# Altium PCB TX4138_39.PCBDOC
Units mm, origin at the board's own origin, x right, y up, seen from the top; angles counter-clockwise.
Board outline 46.99 x 45.72 mm, 2 copper layers (TopLayer, BottomLayer); 17 components, 15 nets, 50 pads, 35 vias.
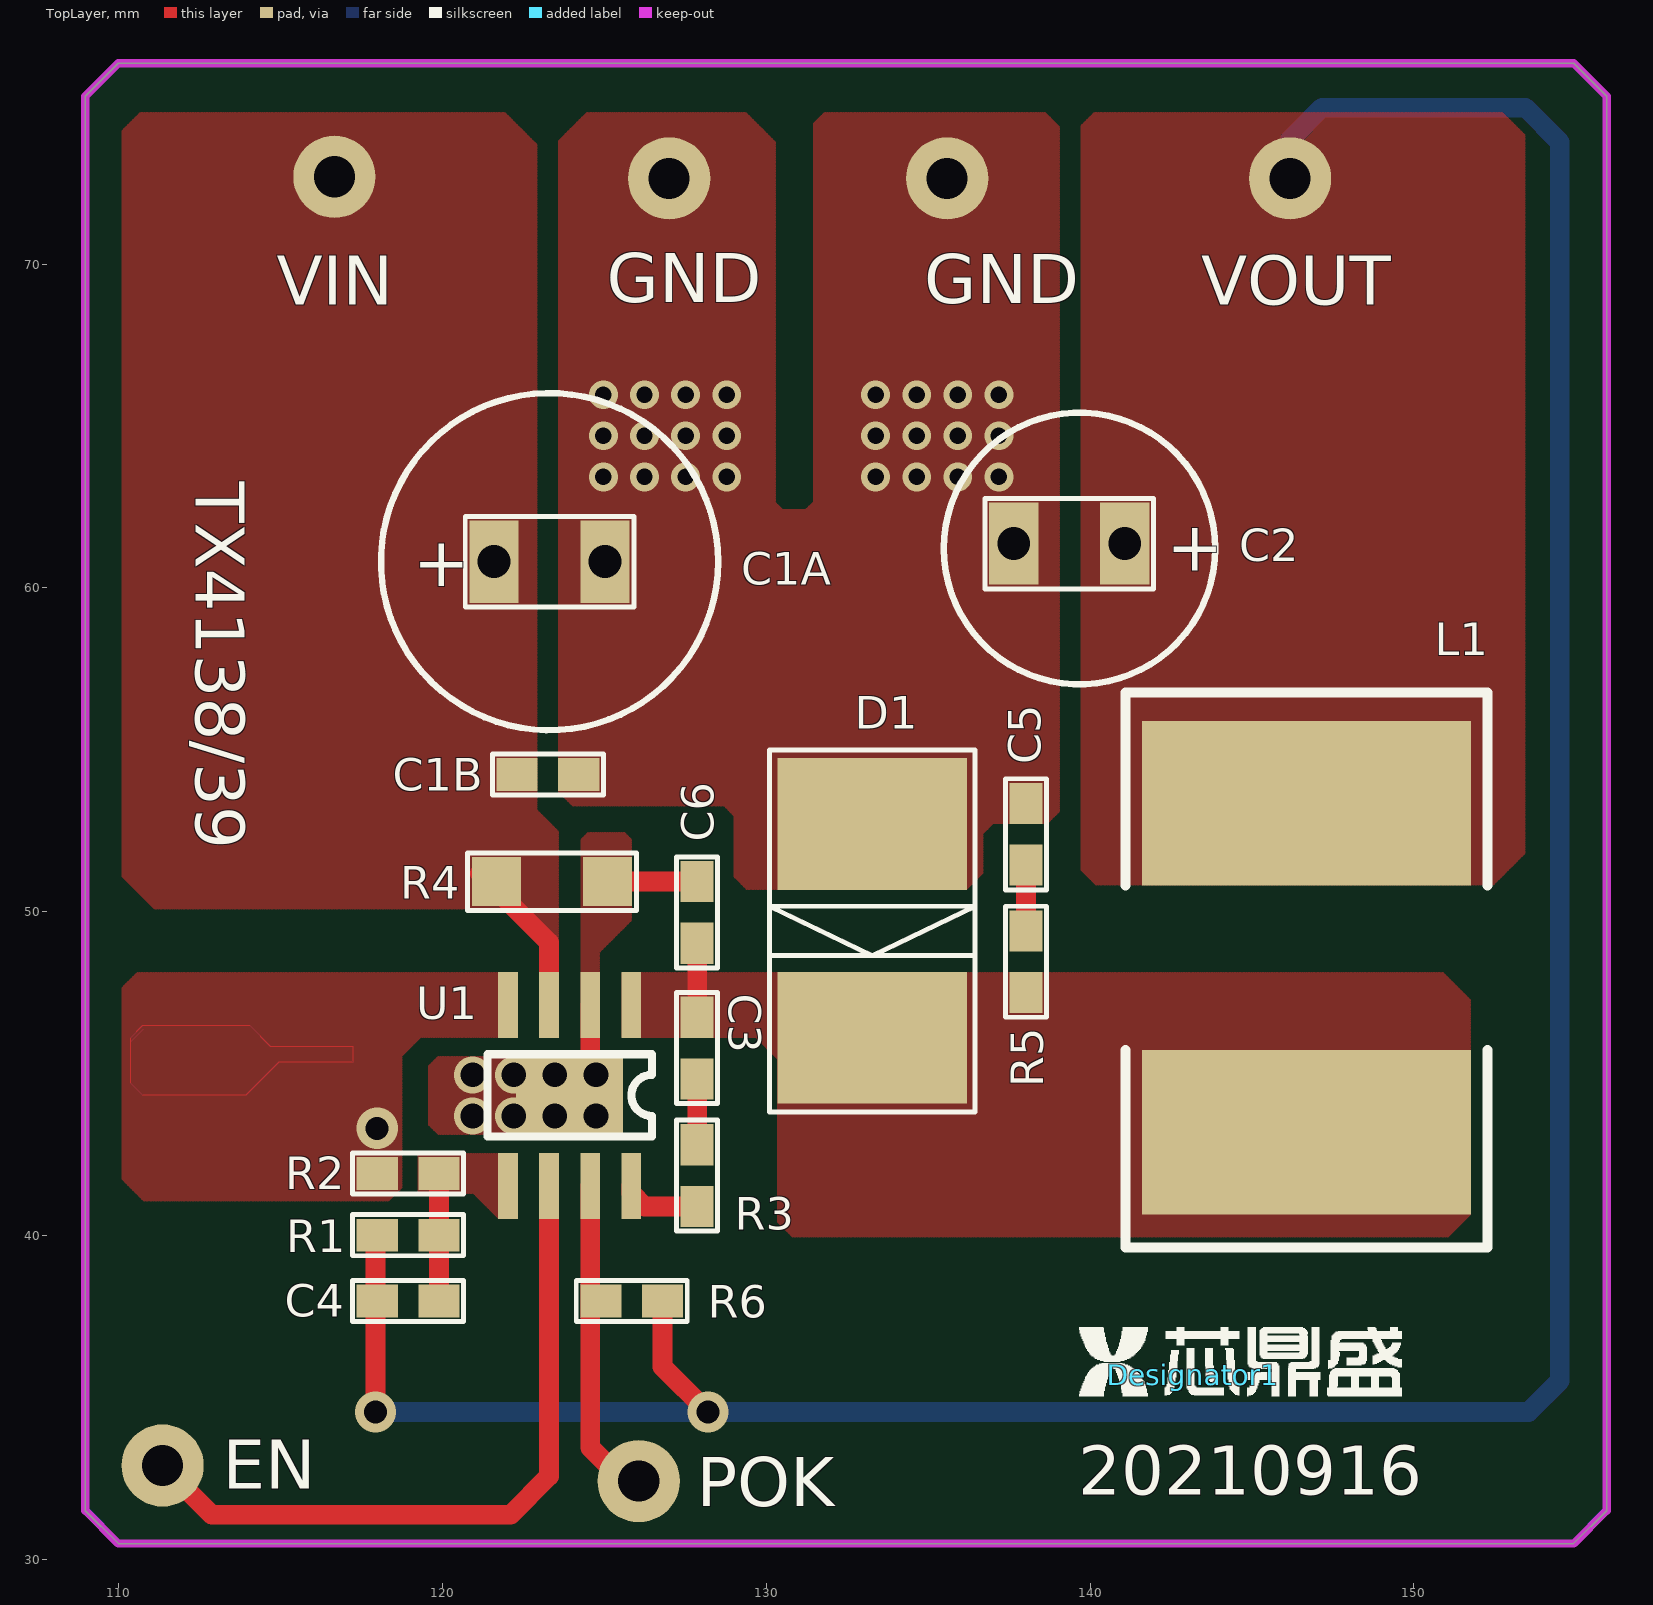
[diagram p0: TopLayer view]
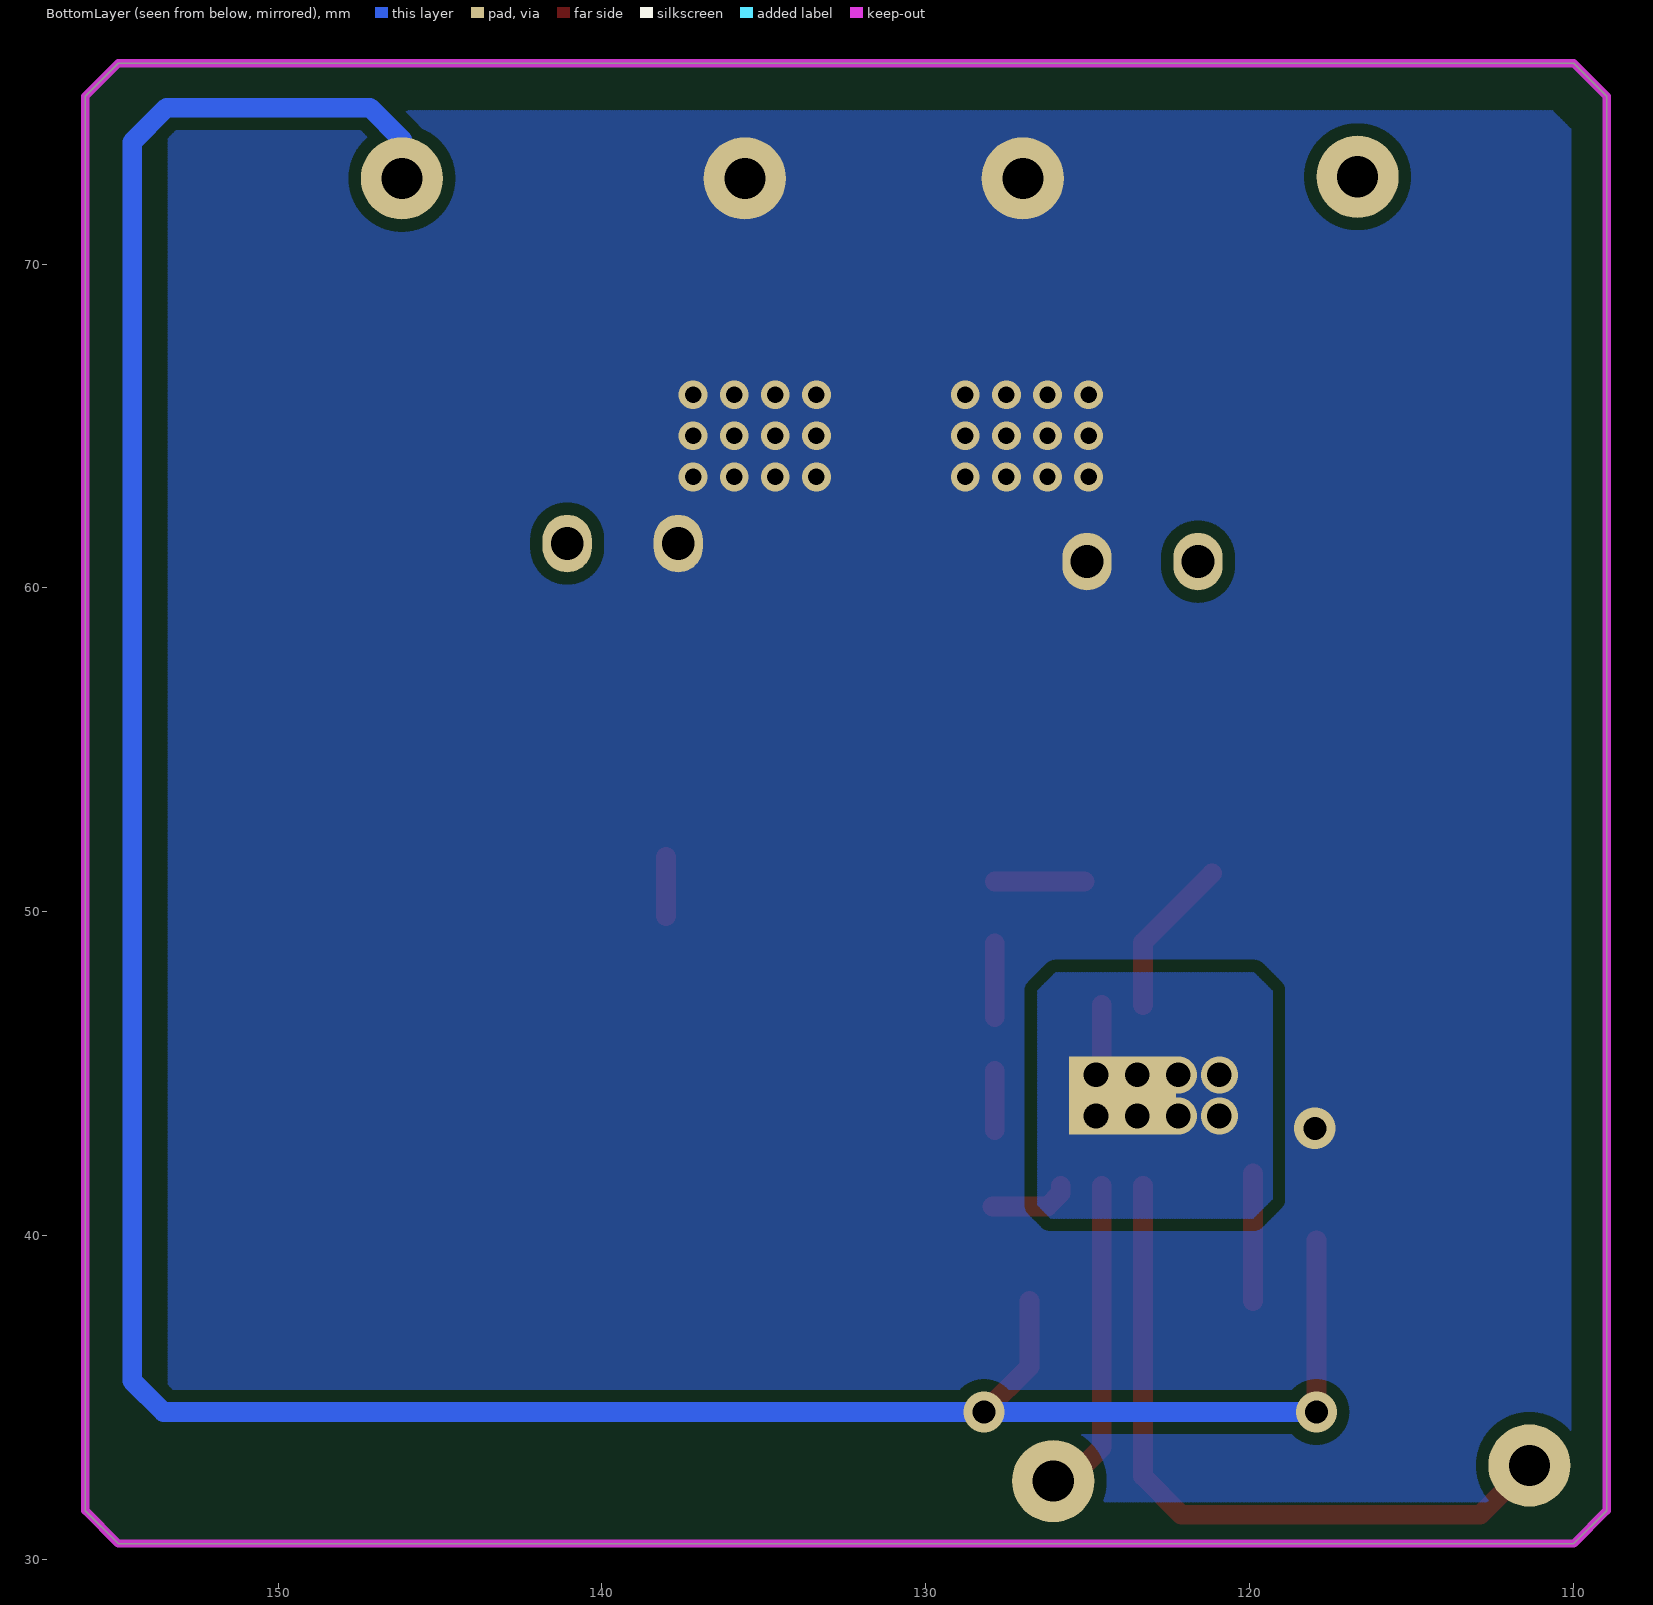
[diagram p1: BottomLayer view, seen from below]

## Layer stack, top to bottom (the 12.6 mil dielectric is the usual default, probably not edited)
TopSolder: solder mask 0.0102, Solder Resist, Dk 3.5
TopLayer: signal copper 0.0356
Dielectric1: dielectric 0.32, FR-4, Dk 4.8
BottomLayer: signal copper 0.0356
BottomSolder: solder mask 0.0102, Solder Resist, Dk 3.5

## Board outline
108.966,31.496 108.966,75.184 109.982,76.2 154.94,76.2 155.956,75.184 155.956,31.496 154.94,30.48 109.982,30.48

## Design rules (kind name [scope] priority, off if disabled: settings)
Clearance Clearance_1 [OnLayer('BottomLayer')] p1: gap=0.381 ignorepadtopadclearanceinfootprint=FALSE
Clearance [All] p2: gap=0.254 ignorepadtopadclearanceinfootprint=FALSE
FabricationTestPointUsage TestPointUsage [All] p1: valid=0 allowmultiple=FALSE
FabricationTestpoint Testpoint [All] p1: side=3 testpointundercomponent=TRUE minsize=1.016 maxsize=2.54 preferedsize=1.524 minholesize=0.508 maxholesize=1.016 preferedholesize=0.813 testpointgrid=0.025 allowsidetop=TRUE allowsidebottom=TRUE usegrid=TRUE gridtolerance=0
PolygonConnect [All] p1: connectstyle=Direct reliefconductorwidth=0.254 reliefentries=4 polygonreliefangle="90 Angle" airgapwidth=0.254
RoutingVias [All] p1: holewidth=0.508 width=0.889 viastyle="Through Hole" minholewidth=0.711 minwidth=1.27 maxholewidth=0.711 maxwidth=1.27
SolderMaskExpansion [All] p1: expansion=0.102 istentingtop=FALSE
Width [All] p1: maxlimit=1.27 minlimit=0.254 preferedwidth=0.61
28 further rules are at their usual default settings.

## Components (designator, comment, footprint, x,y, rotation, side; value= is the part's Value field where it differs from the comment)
C1A "10uF/50V" 1210 121.59,60.808 r0 top
C1B "100nF" 0603 122.301,54.229 r0 top
C2 "22uF/25V" 1210 141.072,61.366 r180 top
C3 "30R" 0603 127.864,44.831 r90 top
C4 "300K" 0603 117.983,37.973 r0 top
C5 "30R" 0603 138.024,51.435 r90 top
C6 "100nF" 0603 127.864,49.022 r90 top
D1 "SK34B" SMC 133.274,52.705 r270 top
Designator1 "Comment" LOGO(10x2)mm 143.18,35.69 r0 top
L1 "" CD125 146.685,43.18 r90 top
R1 "22pF" 0603 117.983,40.005 r0 top
R2 "57.1K" 0603 119.888,41.91 r180 top
R3 "10nF" 0603 127.864,42.799 r270 top
R4 "R040" 1206 125.095,50.927 r180 top
R5 "10nF" 0603 138.024,49.403 r270 top
R6 "22pF" 0603 126.797,37.973 r180 top
U1 "" ESOP-8 125.832,47.117 r270 top

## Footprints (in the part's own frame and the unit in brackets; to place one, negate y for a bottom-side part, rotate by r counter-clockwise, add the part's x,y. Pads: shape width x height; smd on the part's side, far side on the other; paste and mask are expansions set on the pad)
0603 [mil]
  rect 50x40 smd: 1(0,0) 2(75,0)
  silkscreen extent -30,-25 105,25
1206 [mil]
  rect 60x60 smd: 1(0,0) 2(135,0)
  silkscreen extent -35,-35 170,35
1210 [mil]
  rect 60x100 smd: 1(0,0) 2(135,0)
  silkscreen extent -35,-55 170,55
CD125 [mm]
  rect 5.08x10.16 smd: 1(0,0) 2(10.16,0)
  silkscreen extent -3.56,-5.59 13.59,5.59
ESOP-8 [mil]
  rect 80x24 smd: 1(0,0) 2(0,-50) 3(0,-100) 4(0,-150) 5(220,-150) 6(220,-100) 7(220,-50) 8(220,0)
  rect 95x130 smd: 9(110,-75)
  rect 95x130 smd far side: 9(110,-75)
  silkscreen extent 60,-175 160,25
LOGO(10x2)mm [mm]
  silkscreen extent -3.52,-0.65 6.44,1.47
SMC [mil]
  rect 160x230 smd: 1(0,0) 2(260,0)
  silkscreen extent -90,-125 350,125

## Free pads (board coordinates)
  round 2.54 hole 1.27: 1(111.354,32.893) 1(116.662,72.695) 1(126.06,32.41) 1(127,72.644) 1(135.585,72.644) 1(146.177,72.644)
  oval 1.524x1.778 hole 1.016: 1(121.59,60.808) 1(137.643,61.366) ""(125.019,60.808) ""(141.072,61.366)

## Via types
v1: diameter 0.889, hole 0.508, TopLayer to BottomLayer, 24 vias
v2: diameter 1.143, hole 0.762, TopLayer to BottomLayer, 8 vias
v3: diameter 1.27, hole 0.711, TopLayer to BottomLayer, 3 vias

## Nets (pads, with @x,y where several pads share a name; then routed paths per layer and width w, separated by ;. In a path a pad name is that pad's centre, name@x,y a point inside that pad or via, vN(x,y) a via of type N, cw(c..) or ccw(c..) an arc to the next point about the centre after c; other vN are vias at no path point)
BST: R3.2 U1.8 | length 2.5
  TopLayer w0.61: U1.8 125.832,41.3 126.238,40.894 R3.2@127.94,40.894
EN: pad.1@111.354,32.893 U1.6 | length 22
  TopLayer w0.61: pad.1@111.354,32.893 112.878,31.369 122.098,31.369 123.292,32.563 U1.6
EN1: 
FB: C4.2 R1.2 R2.1 U1.5 | length 3.9
  TopLayer w0.61: C4.2 R2.1
GATE: 
GND: C1A.2 C1B.2 C2.2 C5.2 D1.1 pad.1@127,72.644 pad.1@135.585,72.644 pad.1@137.643,61.366 pad.@125.019,60.808 R2.2 U1.4
  other v1: 124.968,63.424 126.238,63.424 127.508,63.424 128.778,63.424 133.375,63.424 134.645,63.424 135.915,63.424 137.185,63.424 124.968,64.694 126.238,64.694 127.508,64.694 128.778,64.694 133.375,64.694 134.645,64.694 135.915,64.694 137.185,64.694 124.968,65.964 126.238,65.964 127.508,65.964 128.778,65.964 133.375,65.964 134.645,65.964 135.915,65.964 137.185,65.964
  other v3: 117.983,43.307
ILIM: C6.2 R4.1 U1.2 U1.9 | length 5.8
  TopLayer w0.61: U1.9@123.927,44.323 124.562,44.958 U1.2 ; R4.1 C6.2
  other v2: 120.929,43.688 122.199,43.688 123.469,43.688 124.739,43.688 120.929,44.958 122.199,44.958 123.469,44.958 124.739,44.958
OUT: C2.1 C4.1 L1.2 pad.1@146.177,72.644 pad.@141.072,61.366 R1.1 R6.1 | length 95
  TopLayer w0.61: v3(117.932,34.544) R1.1@117.932,39.853 ; R6.1 126.797,35.941 v3(128.194,34.544)
  BottomLayer w0.61: v3@117.907,34.569 v3(117.932,34.544) 153.543,34.544 154.508,35.509 154.508,73.762 153.441,74.828 147.168,74.828 146.177,73.838 pad.1@146.177,72.644
POK: pad.1@126.06,32.41 R6.2 U1.7 | length 10
  TopLayer w0.61: U1.7 124.562,33.452 125.603,32.41 pad.1@126.06,32.41
RC1: 
SS: 
SW: C3.2 C6.1 D1.2 L1.1 R5.2 U1.1 | length 2.3
  TopLayer w0.61: C3.2 C6.1
sw-bst: C3.1 R3.1 | length 1.8
  TopLayer w0.61: R3.1@127.864,43.256 C3.1@127.864,45.085
VIN: C1A.1 C1B.1 pad.1@116.662,72.695 pad.1@121.59,60.808 R4.2 U1.3 | length 4.9
  TopLayer w0.61: R4.2@121.158,51.181 123.292,49.047 U1.3
VPOK: 
pads on no net: C5.1 R5.1
copper on no net: | length 1.8
  TopLayer w0.61: 138.024,49.86 138.024,51.689

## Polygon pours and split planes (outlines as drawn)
GND on TopLayer "TopLayer-GND" (hatched 90Degree grid 0.025 track 0.051, remove dead copper, pour order 0): 131.47,69.723 131.47,71.831 139.04,71.831 139.04,69.723
GND on TopLayer "TopLayer-GND 1" (hatched 90Degree grid 0.025 track 0.051, remove dead copper, pour order 1): 122.301,46.126 119.329,46.126 118.745,45.542 118.745,41.478 118.339,41.072 110.769,41.072 110.109,41.732 110.109,47.65 110.566,48.108 122.301,48.108
ILIM on TopLayer "TopLayer-ILIM" (hatched 90Degree grid 0.025 track 0.051, remove dead copper, pour order 2): 125.552,45.517 119.863,45.517 119.583,45.237 119.583,43.409 119.863,43.129 125.552,43.129
FB on TopLayer "TopLayer-FB" (hatched 90Degree grid 0.025 track 0.051, remove dead copper, pour order 3): 122.301,42.52 119.253,42.52 119.253,41.3 120.955,41.3 121.717,40.538 122.301,40.538
GND on TopLayer "TopLayer-GND 2" (hatched 90Degree grid 0.025 track 0.051, remove dead copper, pour order 4): 134.29,70.993 138.532,70.993 139.04,71.501 139.04,74.244 138.608,74.676 131.801,74.676 131.47,74.346 131.47,71.476 131.953,70.993
GND on TopLayer "TopLayer-GND 3" (hatched 90Degree grid 0.025 track 0.051, remove dead copper, pour order 5): 132.994,50.698 136.195,50.698 136.677,51.181 136.677,52.4 137.008,52.73 138.684,52.73 139.04,53.086 139.04,69.952 131.47,69.952 131.47,62.662 131.216,62.408 130.505,62.408 130.277,62.636 130.277,73.762 129.362,74.676 124.46,74.676 123.596,73.812 123.596,53.696 124.028,53.264 128.702,53.264 129.007,52.959 129.007,51.079 129.388,50.698
OUT on TopLayer "TopLayer-OUT" (hatched 90Degree grid 0.025 track 0.051, remove dead copper, pour order 6): 139.725,58.623 139.725,51.283 140.183,50.825 152.451,50.825 153.416,51.791 153.416,73.99 152.73,74.676 140.132,74.676 139.725,74.27 139.725,65.405 139.725,60.198
VIN on TopLayer "TopLayer-VIN" (hatched 90Degree grid 0.025 track 0.051, remove dead copper, pour order 7): 123.571,48.412 123.571,52.476 122.911,53.137 122.911,73.685 121.92,74.676 110.668,74.676 110.109,74.117 110.109,51.079 111.1,50.089 121.895,50.089
SW on TopLayer "TopLayer-SW" (hatched 90Degree grid 0.025 track 0.051, remove dead copper, pour order 8): 125.552,48.108 150.901,48.108 151.74,47.269 151.74,40.64 151.054,39.954 130.81,39.954 130.353,40.411 130.353,45.441 129.667,46.126 125.552,46.126
GND on TopLayer "TopLayer-GND 4" (hatched 90Degree grid 0.025 track 0.051, remove dead copper, pour order 9): 125.705,48.285
VIN on TopLayer "TopLayer-VIN 1" (hatched 90Degree grid 0.025 track 0.051, remove dead copper, pour order 10): 126.721,49.53
SW on TopLayer "TopLayer-SW 1" (hatched 90Degree grid 0.025 track 0.051, remove dead copper, pour order 11): 140.36,53.645
SW on TopLayer "TopLayer-SW 2" (hatched 90Degree grid 0.025 track 0.203, pour order 12): 47.117,38.862
SW on TopLayer "TopLayer-SW 3" (hatched 90Degree grid 0.102 track 0.025, remove dead copper, pour order 13): 47.117,41.783
VIN on TopLayer "TopLayer-VIN 2" (hatched 90Degree grid 0.025 track 0.102, remove dead copper, pour order 14): 41.656,41.021
VIN on TopLayer "TopLayer-VIN 3" (hatched 90Degree grid 0.025 track 0.102, remove dead copper, pour order 15): 28.067,45.212
VIN on TopLayer "TopLayer-VIN 4" (hatched 90Degree grid 0.025 track 0.102, remove dead copper, pour order 16): 73.66,41.783 72.136,41.783 71.374,41.021 71.374,39.878 70.231,38.735 56.515,38.735 55.372,37.592 52.578,37.592 51.816,36.83
VIN on TopLayer "TopLayer-VIN 5" (hatched 90Degree grid 0.025 track 0.102, remove dead copper, pour order 17): 116.967,45.339 114.935,45.339 113.919,44.323 110.744,44.323 110.363,44.704 110.363,45.974 110.744,46.355 110.363,45.974 110.363,46.101 110.744,46.482 114.046,46.482 114.681,45.847 117.221,45.847 117.221,45.339
ILIM on TopLayer "TopLayer-ILIM 1" (hatched 90Degree grid 0.025 track 0.051, remove dead copper, pour order 18): 124.282,46.126 124.841,46.126 124.841,48.743 125.832,49.733 125.832,52.222 125.628,52.426 124.485,52.426 124.282,52.222
ILIM on BottomLayer "BottomLayer-ILIM" (hatched 90Degree grid 0.025 track 0.051, remove dead copper, pour order 19): 119.304,47.346 119.304,41.123 119.888,40.538 126.136,40.538 126.543,40.945 126.543,47.549 125.984,48.108 119.863,48.108 119.304,47.549
VIN on BottomLayer "BottomLayer-VIN" (hatched 90Degree grid 0.025 track 0.102, remove dead copper, pour order 20): 27.432,54.864 26.289,53.721
GND on BottomLayer "BottomLayer-GND" (hatched 90Degree grid 0.025 track 0.102, remove dead copper, pour order 21): 126.111,49.53
GND on BottomLayer "BottomLayer-GND 1" (hatched 90Degree grid 0.025 track 0.051, remove dead copper, pour order 22): 112.878,74.727 152.705,74.727 153.391,74.041 153.391,32.715 152.451,31.775 110.795,31.775 110.084,32.487 110.084,74.168 110.642,74.727
ILIM on TopSolder (hatched 90Degree grid 0.025 track 0.051, remove dead copper): 120.752,45.568 122.809,45.568 122.809,43.078 119.837,43.078 119.532,43.383 119.532,45.263 119.837,45.568
ILIM on BottomSolder (hatched 90Degree grid 0.025 track 0.051, remove dead copper): 120.167,40.488 126.162,40.488 126.594,40.919 126.594,47.574 126.009,48.158 119.837,48.158 119.253,47.574 119.253,41.097 119.863,40.488

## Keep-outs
KeepOutLayer:
  the board outline again, w0.254

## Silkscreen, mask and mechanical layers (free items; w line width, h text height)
TopOverlay:
  circle w0.2: c139.675,61.214 r4.191
  circle w0.2: c123.304,60.808 r5.207
  text "GND" at 125.07,68.814 h1.52
  text "GND" at 134.874,68.789 h1.52
  text "VIN" at 114.884,68.738 h1.52
  text "VOUT" at 143.434,68.738 h1.52
  text "TX4138/39" at 112.374,63.276 h1.52 r270
  text "+" at 142.367,60.528 h1.52
  text "+" at 119.101,60.046 h1.52
  text "EN" at 113.208,32.182 h1.52
  text "20210916" at 139.634,31.994 h1.52
  text "POK" at 127.844,31.634 h1.52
